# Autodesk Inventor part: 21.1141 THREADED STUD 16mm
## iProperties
Created: 2007-03
Part Number: 21.1141 THREADED STUD 16mm
Document SubType Name: Modeling
Designer: Andy Moles
Material: Steel
Mass: 331.098 g
Surface Area: 107.562 cm^2
Volume: 42.1781 cm^3
Density: 7.85 g/cm^3
Author: Andy Moles
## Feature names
1. Revolution1
2. Extrusion1
3. Extrusion2
4. Extrusion3
5. Chamfer1
